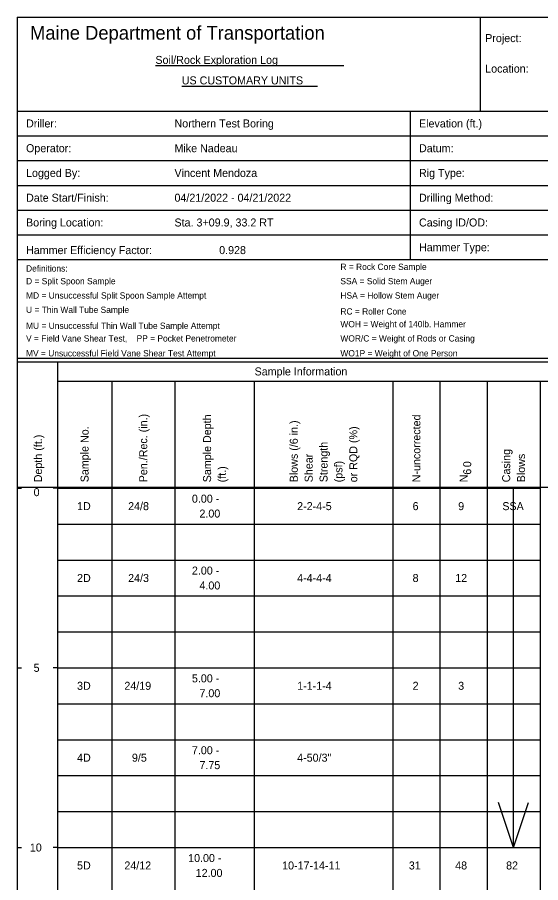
# Model space of a CAD drawing. Extents: x 9422 to 9552, y 6780 to 6860.
# Drawn here: x 9498.16 to 9512.73, y 6835.99 to 6860.07 of the extents above; entities that cross this region are included whole.
import ezdxf

# ---------------------------------------------------------------- set-up
doc = ezdxf.new("R2010")
doc.units = 0
doc.layers.add('7', color=7, linetype='Continuous')

msp = doc.modelspace()

# ---------------------------------------------------------------- linework, layer by layer
at = {"layer": '7'}
for p, q in [((9502.002, 6858.729), (9507.244, 6858.729)), ((9502.736, 6858.16), (9506.51, 6858.16)), ((9511.973, 6836.968), (9511.973, 6846.968)), ((9511.973, 6836.968), (9511.556, 6838.218)), ((9511.973, 6836.968), (9512.389, 6838.218))]:
    msp.add_line(p, q, dxfattribs=at)
for points in [[(9498.158, 6860.072), (9498.158, 6816.552)], [(9498.158, 6860.072), (9529.654, 6860.072)], [(9511.04, 6860.072), (9511.04, 6857.463)], [(9498.158, 6857.463), (9529.654, 6857.463)], [(9509.095, 6857.463), (9509.095, 6854.018)], [(9498.158, 6856.774), (9529.654, 6856.774)], [(9498.158, 6856.085), (9529.654, 6856.085)], [(9498.158, 6855.396), (9529.654, 6855.396)], [(9498.158, 6854.707), (9529.654, 6854.707)], [(9498.158, 6854.018), (9529.654, 6854.018)], [(9509.095, 6854.018), (9509.095, 6853.328)], [(9498.158, 6853.328), (9529.654, 6853.328)], [(9498.158, 6850.59), (9529.654, 6850.59)], [(9498.158, 6850.486), (9529.654, 6850.486)], [(9499.276, 6850.486), (9499.276, 6821.941)], [(9499.276, 6849.95), (9514.023, 6849.95)], [(9500.785, 6849.95), (9500.785, 6821.941)], [(9502.54, 6849.95), (9502.54, 6821.941)], [(9504.755, 6849.95), (9504.755, 6821.941)], [(9508.61, 6849.95), (9508.61, 6821.941)], [(9509.922, 6849.95), (9509.922, 6821.941)], [(9511.234, 6849.95), (9511.234, 6821.941)], [(9512.711, 6849.95), (9512.711, 6821.941)], [(9498.158, 6846.996), (9529.654, 6846.996)], [(9498.158, 6846.968), (9498.279, 6846.968)], [(9499.276, 6846.968), (9499.154, 6846.968)], [(9499.276, 6846.968), (9500.785, 6846.968)], [(9500.785, 6846.968), (9502.54, 6846.968)], [(9502.54, 6846.968), (9504.755, 6846.968)], [(9504.755, 6846.968), (9508.61, 6846.968)], [(9508.61, 6846.968), (9509.922, 6846.968)], [(9509.922, 6846.968), (9511.234, 6846.968)], [(9511.234, 6846.968), (9512.711, 6846.968)], [(9499.276, 6845.968), (9500.785, 6845.968)], [(9500.785, 6845.968), (9502.54, 6845.968)], [(9502.54, 6845.968), (9504.755, 6845.968)], [(9504.755, 6845.968), (9508.61, 6845.968)], [(9508.61, 6845.968), (9509.922, 6845.968)], [(9509.922, 6845.968), (9511.234, 6845.968)], [(9511.234, 6845.968), (9512.711, 6845.968)], [(9499.276, 6844.968), (9500.785, 6844.968)], [(9500.785, 6844.968), (9502.54, 6844.968)], [(9502.54, 6844.968), (9504.755, 6844.968)], [(9504.755, 6844.968), (9508.61, 6844.968)], [(9508.61, 6844.968), (9509.922, 6844.968)], [(9509.922, 6844.968), (9511.234, 6844.968)], [(9511.234, 6844.968), (9512.711, 6844.968)], [(9499.276, 6843.968), (9500.785, 6843.968)], [(9500.785, 6843.968), (9502.54, 6843.968)], [(9502.54, 6843.968), (9504.755, 6843.968)], [(9504.755, 6843.968), (9508.61, 6843.968)], [(9508.61, 6843.968), (9509.922, 6843.968)], [(9509.922, 6843.968), (9511.234, 6843.968)], [(9511.234, 6843.968), (9512.711, 6843.968)], [(9499.276, 6842.968), (9500.785, 6842.968)], [(9500.785, 6842.968), (9502.54, 6842.968)], [(9502.54, 6842.968), (9504.755, 6842.968)], [(9504.755, 6842.968), (9508.61, 6842.968)], [(9508.61, 6842.968), (9509.922, 6842.968)], [(9509.922, 6842.968), (9511.234, 6842.968)], [(9511.234, 6842.968), (9512.711, 6842.968)], [(9498.158, 6841.968), (9498.279, 6841.968)], [(9499.276, 6841.968), (9499.154, 6841.968)], [(9499.276, 6841.968), (9500.785, 6841.968)], [(9500.785, 6841.968), (9502.54, 6841.968)], [(9502.54, 6841.968), (9504.755, 6841.968)], [(9504.755, 6841.968), (9508.61, 6841.968)], [(9508.61, 6841.968), (9509.922, 6841.968)], [(9509.922, 6841.968), (9511.234, 6841.968)], [(9511.234, 6841.968), (9512.711, 6841.968)], [(9499.276, 6840.968), (9500.785, 6840.968)], [(9500.785, 6840.968), (9502.54, 6840.968)], [(9502.54, 6840.968), (9504.755, 6840.968)], [(9504.755, 6840.968), (9508.61, 6840.968)], [(9508.61, 6840.968), (9509.922, 6840.968)], [(9509.922, 6840.968), (9511.234, 6840.968)], [(9511.234, 6840.968), (9512.711, 6840.968)], [(9499.276, 6839.968), (9500.785, 6839.968)], [(9500.785, 6839.968), (9502.54, 6839.968)], [(9502.54, 6839.968), (9504.755, 6839.968)], [(9504.755, 6839.968), (9508.61, 6839.968)], [(9508.61, 6839.968), (9509.922, 6839.968)], [(9509.922, 6839.968), (9511.234, 6839.968)], [(9511.234, 6839.968), (9512.711, 6839.968)], [(9499.276, 6838.968), (9500.785, 6838.968)], [(9500.785, 6838.968), (9502.54, 6838.968)], [(9502.54, 6838.968), (9504.755, 6838.968)], [(9504.755, 6838.968), (9508.61, 6838.968)], [(9508.61, 6838.968), (9509.922, 6838.968)], [(9509.922, 6838.968), (9511.234, 6838.968)], [(9511.234, 6838.968), (9512.711, 6838.968)], [(9499.276, 6837.968), (9500.785, 6837.968)], [(9500.785, 6837.968), (9502.54, 6837.968)], [(9502.54, 6837.968), (9504.755, 6837.968)], [(9504.755, 6837.968), (9508.61, 6837.968)], [(9508.61, 6837.968), (9509.922, 6837.968)], [(9509.922, 6837.968), (9511.234, 6837.968)], [(9511.234, 6837.968), (9512.711, 6837.968)], [(9498.158, 6836.968), (9498.279, 6836.968)], [(9499.276, 6836.968), (9499.154, 6836.968)], [(9499.276, 6836.968), (9500.785, 6836.968)], [(9500.785, 6836.968), (9502.54, 6836.968)], [(9502.54, 6836.968), (9504.755, 6836.968)], [(9504.755, 6836.968), (9508.61, 6836.968)], [(9508.61, 6836.968), (9509.922, 6836.968)], [(9509.922, 6836.968), (9511.234, 6836.968)], [(9511.234, 6836.968), (9512.711, 6836.968)]]:
    msp.add_lwpolyline(points, dxfattribs=at)

# ---------------------------------------------------------------- texts
for s, height, p in [('Maine Department of Transportation', 0.38194, (9498.512, 6859.45)), ('Project:', 0.2228, (9511.182, 6859.382)), ('Soil/Rock Exploration Log', 0.2228, (9502.002, 6858.775)), ('Location:', 0.2228, (9511.182, 6858.533)), ('US CUSTOMARY UNITS', 0.2228, (9502.736, 6858.205)), ('Driller:', 0.2228, (9498.401, 6857.007)), ('Northern Test Boring', 0.2228, (9502.533, 6857.007)), ('Elevation (ft.)', 0.2228, (9509.339, 6857.007)), ('Operator:', 0.2228, (9498.401, 6856.318)), ('Mike Nadeau', 0.2228, (9502.533, 6856.318)), ('Datum:', 0.2228, (9509.339, 6856.318)), ('Logged By:', 0.2228, (9498.401, 6855.629)), ('Vincent Mendoza', 0.2228, (9502.533, 6855.629)), ('Rig Type:', 0.2228, (9509.339, 6855.629)), ('Date Start/Finish:', 0.2228, (9498.401, 6854.94)), ('04/21/2022 - 04/21/2022', 0.2228, (9502.533, 6854.94)), ('Drilling Method:', 0.2228, (9509.339, 6854.94)), ('Boring Location:', 0.2228, (9498.401, 6854.251)), ('Sta. 3+09.9, 33.2 RT', 0.2228, (9502.533, 6854.251)), ('Casing ID/OD:', 0.2228, (9509.339, 6854.251)), ('Hammer Type:', 0.2228, (9509.339, 6853.562)), ('Hammer Efficiency Factor:', 0.2228, (9498.401, 6853.482)), ('0.928', 0.2228, (9503.777, 6853.482)), ('Definitions:', 0.17506, (9498.401, 6852.996)), ('R = Rock Core Sample', 0.17506, (9507.151, 6853.042)), ('D = Split Spoon Sample', 0.17506, (9498.401, 6852.643)), ('SSA = Solid Stem Auger', 0.17506, (9507.151, 6852.643)), ('MD = Unsuccessful Split Spoon Sample Attempt', 0.17506, (9498.401, 6852.244)), ('HSA = Hollow Stem Auger', 0.17506, (9507.151, 6852.244)), ('U = Thin Wall Tube Sample', 0.17506, (9498.401, 6851.846)), ('RC = Roller Cone', 0.17506, (9507.151, 6851.8)), ('WOH = Weight of 140lb. Hammer', 0.17506, (9507.151, 6851.447)), ('MU = Unsuccessful Thin Wall Tube Sample Attempt', 0.17506, (9498.401, 6851.402)), ('V = Field Vane Shear Test,    PP = Pocket Penetrometer', 0.17506, (9498.401, 6851.049)), ('WOR/C = Weight of Rods or Casing', 0.17506, (9507.151, 6851.049)), ('MV = Unsuccessful Field Vane Shear Test Attempt', 0.17506, (9498.401, 6850.635)), ('WO1P = Weight of One Person', 0.17506, (9507.151, 6850.635)), ('Sample Information', 0.2228, (9504.762, 6850.106)), ('0', 0.223, (9498.612, 6846.746)), ('0.00 -', 0.2228, (9503.018, 6846.564)), ('1D', 0.2228, (9499.821, 6846.357)), ('24/8', 0.2228, (9501.243, 6846.357)), ('2-2-4-5', 0.2228, (9505.948, 6846.357)), ('6', 0.223, (9509.161, 6846.357)), ('  9', 0.2228, (9510.264, 6846.357)), ('SSA', 0.2228, (9511.658, 6846.357)), ('2.00', 0.2228, (9503.228, 6846.15)), ('2.00 -', 0.2228, (9503.018, 6844.564)), ('2D', 0.2228, (9499.821, 6844.357)), ('24/3', 0.2228, (9501.243, 6844.357)), ('4.00', 0.2228, (9503.228, 6844.15)), ('4-4-4-4', 0.2228, (9505.948, 6844.357)), ('8', 0.223, (9509.161, 6844.357)), (' 12', 0.2228, (9510.264, 6844.357)), ('5', 0.223, (9498.612, 6841.857)), ('5.00 -', 0.2228, (9503.018, 6841.564)), ('3D', 0.2228, (9499.821, 6841.357)), ('24/19', 0.2228, (9501.138, 6841.357)), ('1-1-1-4', 0.2228, (9505.948, 6841.357)), ('2', 0.223, (9509.161, 6841.357)), ('  3', 0.2228, (9510.264, 6841.357)), ('7.00', 0.2228, (9503.228, 6841.15)), ('4D', 0.2228, (9499.821, 6839.357)), ('9/5', 0.2228, (9501.348, 6839.357)), ('7.00 -', 0.2228, (9503.018, 6839.564)), ('4-50/3"', 0.2228, (9505.948, 6839.357)), ('7.75', 0.2228, (9503.228, 6839.15)), ('10', 0.2228, (9498.507, 6836.857)), ('10.00 -', 0.2228, (9502.913, 6836.564)), ('5D', 0.2228, (9499.821, 6836.357)), ('24/12', 0.2228, (9501.138, 6836.357)), ('10-17-14-11', 0.2228, (9505.529, 6836.357)), ('31', 0.2228, (9509.056, 6836.357)), (' 48', 0.2228, (9510.264, 6836.357)), ('82', 0.2228, (9511.763, 6836.357)), ('12.00', 0.2228, (9503.123, 6836.15))]:
    msp.add_text(s, height=height, dxfattribs=at).set_placement(p)
for s, height, p in [('Pen./Rec. (in.)', 0.2228, (9501.774, 6847.132)), ('Sample Depth', 0.2228, (9503.552, 6847.132)), ('N-uncorrected', 0.2228, (9509.377, 6847.132)), ('Blows (/6 in.)', 0.2228, (9505.965, 6847.132)), ('Sample No.', 0.2228, (9500.142, 6847.132)), ('or RQD (%%%)', 0.2228, (9507.622, 6847.132)), ('Depth (ft.)', 0.2228, (9498.846, 6847.132)), ('Strength', 0.2228, (9506.794, 6847.132)), ('Casing ', 0.2228, (9511.877, 6847.132)), ('Shear', 0.2228, (9506.379, 6847.132)), ('Blows', 0.2228, (9512.291, 6847.132)), ('(ft.)', 0.2228, (9503.966, 6847.132)), ('(psf)', 0.2228, (9507.208, 6847.132)), ('0', 0.223, (9510.793, 6847.552)), ('N', 0.223, (9510.69, 6847.132)), ('6', 0.223, (9510.793, 6847.342))]:
    msp.add_text(s, height=height, rotation=90, dxfattribs=at).set_placement(p)

doc.saveas('drawing.dxf')
